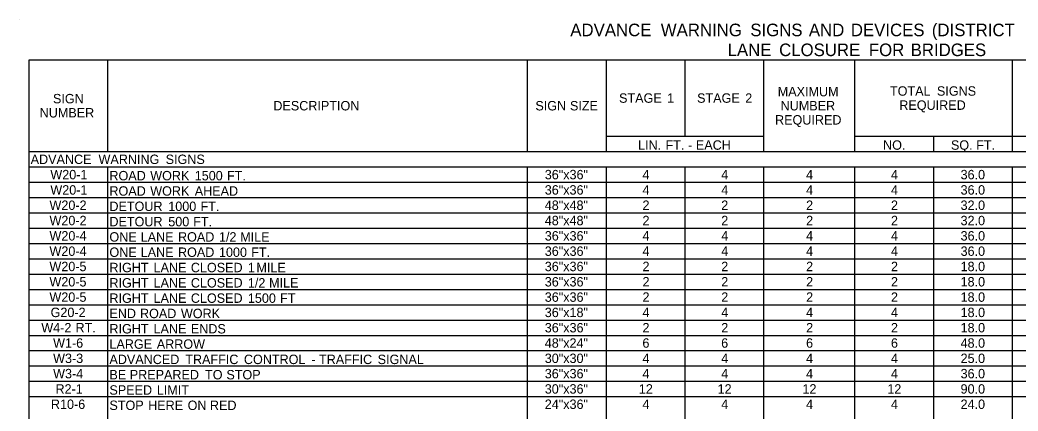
# Model space of a CAD drawing. Extents: x 542596 to 1930787, y -1948294 to 596640.
# Drawn here: x 546357 to 546993, y -1945349 to -1945100 of the extents above; entities that cross this region are included whole.
import ezdxf

# ---------------------------------------------------------------- set-up
doc = ezdxf.new("R2010")
doc.units = 0
doc.layers.add('Default', color=7, linetype='Continuous')

msp = doc.modelspace()

# ---------------------------------------------------------------- linework, layer by layer
at = {"layer": 'Default'}
for p, q in [((546356.95, -1945099.67), (546356.95, -1945099.67)), ((546362.8, -1945125.02), (547426.53, -1945125.02)), ((546362.8, -1945554.02), (546362.8, -1945125.02)), ((546362.8, -1945554.02), (546362.8, -1945125.02)), ((546413.02, -1945183.52), (546413.02, -1945125.02)), ((546680.65, -1945183.52), (546680.65, -1945125.02)), ((546730.87, -1945183.52), (546730.87, -1945125.02)), ((546781.08, -1945173.77), (546781.08, -1945125.02)), ((546831.29, -1945183.52), (546831.29, -1945125.02)), ((546889.3, -1945183.52), (546889.3, -1945125.02)), ((546989.73, -1945183.52), (546989.73, -1945125.02)), ((546730.87, -1945173.77), (546831.29, -1945173.77)), ((546831.29, -1945183.52), (546831.29, -1945173.77)), ((546889.3, -1945173.77), (547426.53, -1945173.77)), ((546939.52, -1945183.52), (546939.52, -1945173.77)), ((546362.8, -1945183.52), (547426.53, -1945183.52)), ((546831.29, -1945183.52), (547426.53, -1945183.52)), ((546362.8, -1945193.27), (547426.53, -1945193.27)), ((546413.02, -1945544.27), (546413.02, -1945193.27)), ((546413.02, -1945544.27), (546413.02, -1945193.27)), ((546680.65, -1945544.27), (546680.65, -1945193.27)), ((546680.65, -1945544.27), (546680.65, -1945193.27)), ((546730.87, -1945544.27), (546730.87, -1945193.27)), ((546730.87, -1945544.27), (546730.87, -1945193.27)), ((546781.08, -1945339.52), (546781.08, -1945193.27)), ((546781.08, -1945544.27), (546781.08, -1945193.27)), ((546831.29, -1945544.27), (546831.29, -1945193.27)), ((546831.29, -1945544.27), (546831.29, -1945193.27)), ((546889.3, -1945544.27), (546889.3, -1945193.27)), ((546939.52, -1945544.27), (546939.52, -1945193.27)), ((546939.52, -1945554.02), (546939.52, -1945193.27)), ((546989.73, -1945554.02), (546989.73, -1945193.27)), ((546989.73, -1945554.02), (546989.73, -1945193.27)), ((546362.8, -1945203.02), (547426.53, -1945203.02)), ((546362.8, -1945212.77), (547426.53, -1945212.77)), ((546362.8, -1945222.52), (547426.53, -1945222.52)), ((546362.8, -1945232.27), (547426.53, -1945232.27)), ((546362.8, -1945242.02), (547426.53, -1945242.02)), ((546362.8, -1945251.77), (547426.53, -1945251.77)), ((546362.8, -1945261.52), (547426.53, -1945261.52)), ((546362.8, -1945271.27), (547426.53, -1945271.27)), ((546362.8, -1945281.02), (547426.53, -1945281.02)), ((546362.8, -1945290.77), (547426.53, -1945290.77)), ((546362.8, -1945300.52), (547426.53, -1945300.52)), ((546362.8, -1945310.27), (547426.53, -1945310.27)), ((546362.8, -1945320.02), (547426.53, -1945320.02)), ((546362.8, -1945329.77), (547426.53, -1945329.77)), ((546362.8, -1945339.52), (547426.53, -1945339.52))]:
    msp.add_line(p, q, dxfattribs=at)

# ---------------------------------------------------------------- texts
for s, height, p in [('ADVANCE', 8, (546707.84, -1945110.01)), (' WARNING', 8, (546762.56, -1945110.01)), (' SIGNS', 8, (546819.63, -1945110.01)), (' AND', 8, (546856.97, -1945110.01)), (' DEVICES', 8, (546883.74, -1945110.01)), (' (DISTRICT', 8, (546935.37, -1945110.01)), ('LANE', 8, (546808.13, -1945122.68)), (' CLOSURE', 8, (546838.01, -1945122.68)), (' FOR', 8, (546895.22, -1945122.68)), (' BRIDGES', 8, (546921.86, -1945122.68)), ('MAXIMUM', 6, (546840.11, -1945148.27)), ('TOTAL', 6, (546911.67, -1945147.9)), (' SIGNS', 6, (546939.36, -1945147.9)), ('SIGN', 6, (546378, -1945152.77)), ('STAGE', 6, (546738.92, -1945152.4)), (' 1', 6, (546767.39, -1945152.4)), ('STAGE', 6, (546788.67, -1945152.4)), (' 2', 6, (546817.13, -1945152.4)), ('NUMBER', 6, (546369.53, -1945161.77)), ('DESCRIPTION', 6, (546518.52, -1945157.27)), ('SIGN', 6, (546685.57, -1945157.27)), (' SIZE', 6, (546705.4, -1945157.27)), ('NUMBER', 6, (546841.92, -1945157.27)), ('REQUIRED', 6, (546917.6, -1945156.9)), ('REQUIRED', 6, (546838.38, -1945166.27)), ('LIN.', 6, (546751.04, -1945182.32)), (' FT.', 6, (546766.3, -1945182.32)), (' -', 6, (546780.62, -1945182.32)), (' EACH', 6, (546785.68, -1945182.32)), ('NO.', 6, (546907.25, -1945182.32)), ('SQ.', 6, (546950.53, -1945182.32)), (' FT.', 6, (546964.39, -1945182.32)), ('ADVANCE', 6, (546363.78, -1945191.4)), (' WARNING', 6, (546404.82, -1945191.4)), (' SIGNS', 6, (546447.62, -1945191.4)), ('W20-1', 6, (546376.34, -1945201.15)), ('ROAD', 6, (546413.99, -1945201.82)), (' WORK', 6, (546437.77, -1945201.82)), (' 1500', 6, (546466.16, -1945201.82)), (' FT.', 6, (546486.72, -1945201.82)), ('36"x36"', 6, (546691.56, -1945201.15)), ('4', 6, (546753.85, -1945201.15)), ('4', 6, (546804.06, -1945201.15)), ('4', 6, (546858.17, -1945201.15)), ('4', 6, (546912.28, -1945201.15)), ('36.0', 6, (546956.67, -1945201.15)), ('W20-1', 6, (546376.34, -1945210.9)), ('ROAD', 6, (546413.99, -1945211.57)), (' WORK', 6, (546437.77, -1945211.57)), (' AHEAD', 6, (546466.16, -1945211.57)), ('36"x36"', 6, (546691.56, -1945210.9)), ('4', 6, (546753.85, -1945210.9)), ('4', 6, (546804.06, -1945210.9)), ('4', 6, (546858.17, -1945210.9)), ('4', 6, (546912.28, -1945210.9)), ('36.0', 6, (546956.67, -1945210.9)), ('W20-2', 6, (546375.79, -1945220.65)), ('DETOUR', 6, (546413.99, -1945221.32)), (' 1000', 6, (546449.28, -1945221.32)), (' FT.', 6, (546469.84, -1945221.32)), ('48"x48"', 6, (546691.56, -1945220.65)), ('2', 6, (546753.86, -1945220.65)), ('2', 6, (546804.08, -1945220.65)), ('2', 6, (546858.19, -1945220.65)), ('2', 6, (546912.3, -1945220.65)), ('32.0', 6, (546956.67, -1945220.65)), ('W20-2', 6, (546375.79, -1945230.4)), ('DETOUR', 6, (546413.99, -1945231.07)), (' 500', 6, (546449.28, -1945231.07)), (' FT.', 6, (546465.18, -1945231.07)), ('48"x48"', 6, (546691.56, -1945230.4)), ('2', 6, (546753.86, -1945230.4)), ('2', 6, (546804.08, -1945230.4)), ('2', 6, (546858.19, -1945230.4)), ('2', 6, (546912.3, -1945230.4)), ('32.0', 6, (546956.67, -1945230.4)), ('W20-4', 6, (546375.77, -1945240.15)), ('ONE', 6, (546413.99, -1945240.82)), (' LANE', 6, (546431.71, -1945240.82)), (' ROAD', 6, (546455.49, -1945240.82)), (' 1/2', 6, (546481.6, -1945240.82)), (' MILE', 6, (546495.13, -1945240.82)), ('36"x36"', 6, (546691.56, -1945240.15)), ('4', 6, (546753.85, -1945240.15)), ('4', 6, (546804.06, -1945240.15)), ('4', 6, (546858.17, -1945240.15)), ('4', 6, (546912.28, -1945240.15)), ('36.0', 6, (546956.67, -1945240.15)), ('W20-4', 6, (546375.77, -1945249.9)), ('ONE', 6, (546413.99, -1945250.57)), (' LANE', 6, (546431.71, -1945250.57)), (' ROAD', 6, (546455.49, -1945250.57)), (' 1000', 6, (546481.6, -1945250.57)), (' FT.', 6, (546502.16, -1945250.57)), ('36"x36"', 6, (546691.56, -1945249.9)), ('4', 6, (546753.85, -1945249.9)), ('4', 6, (546804.06, -1945249.9)), ('4', 6, (546858.17, -1945249.9)), ('4', 6, (546912.28, -1945249.9)), ('36.0', 6, (546956.67, -1945249.9)), ('W20-5', 6, (546375.74, -1945259.65)), ('RIGHT', 6, (546413.99, -1945260.32)), (' LANE', 6, (546439.9, -1945260.32)), (' CLOSED', 6, (546463.68, -1945260.32)), (' 1', 6, (546500.04, -1945260.32)), (' MILE', 6, (546505.49, -1945260.32)), ('36"x36"', 6, (546691.56, -1945259.65)), ('2', 6, (546753.86, -1945259.65)), ('2', 6, (546804.08, -1945259.65)), ('2', 6, (546858.19, -1945259.65)), ('2', 6, (546912.3, -1945259.65)), ('18.0', 6, (546956.67, -1945259.65)), ('W20-5', 6, (546375.74, -1945269.4)), ('RIGHT', 6, (546413.99, -1945270.07)), (' LANE', 6, (546439.9, -1945270.07)), (' CLOSED', 6, (546463.68, -1945270.07)), (' 1/2', 6, (546500.04, -1945270.07)), (' MILE', 6, (546513.57, -1945270.07)), ('36"x36"', 6, (546691.56, -1945269.4)), ('2', 6, (546753.86, -1945269.4)), ('2', 6, (546804.08, -1945269.4)), ('2', 6, (546858.19, -1945269.4)), ('2', 6, (546912.3, -1945269.4)), ('18.0', 6, (546956.67, -1945269.4)), ('W20-5', 6, (546375.74, -1945279.15)), ('RIGHT', 6, (546413.99, -1945279.82)), (' LANE', 6, (546439.9, -1945279.82)), (' CLOSED', 6, (546463.68, -1945279.82)), (' 1500', 6, (546500.04, -1945279.82)), (' FT', 6, (546520.6, -1945279.82)), ('36"x36"', 6, (546691.56, -1945279.15)), ('2', 6, (546753.86, -1945279.15)), ('2', 6, (546804.08, -1945279.15)), ('2', 6, (546858.19, -1945279.15)), ('2', 6, (546912.3, -1945279.15)), ('18.0', 6, (546956.67, -1945279.15)), ('G20-2', 6, (546376.49, -1945288.9)), ('END', 6, (546413.99, -1945289.57)), (' ROAD', 6, (546431.25, -1945289.57)), (' WORK', 6, (546457.35, -1945289.57)), ('36"x18"', 6, (546691.56, -1945288.9)), ('4', 6, (546753.85, -1945288.9)), ('4', 6, (546804.06, -1945288.9)), ('4', 6, (546858.17, -1945288.9)), ('4', 6, (546912.28, -1945288.9)), ('18.0', 6, (546956.67, -1945288.9)), ('W4-2', 6, (546370.57, -1945298.65)), (' RT.', 6, (546390.15, -1945298.65)), ('RIGHT', 6, (546413.99, -1945299.32)), (' LANE', 6, (546439.9, -1945299.32)), (' ENDS', 6, (546463.68, -1945299.32)), ('36"x36"', 6, (546691.56, -1945298.65)), ('2', 6, (546753.86, -1945298.65)), ('2', 6, (546804.08, -1945298.65)), ('2', 6, (546858.19, -1945298.65)), ('2', 6, (546912.3, -1945298.65)), ('18.0', 6, (546956.67, -1945298.65)), ('W1-6', 6, (546378.09, -1945308.4)), ('48"x24"', 6, (546691.56, -1945308.4)), ('6', 6, (546753.83, -1945308.4)), ('6', 6, (546804.04, -1945308.4)), ('6', 6, (546858.16, -1945308.4)), ('6', 6, (546912.27, -1945308.4)), ('48.0', 6, (546956.67, -1945308.4)), ('LARGE', 6, (546413.99, -1945309.07)), (' ARROW', 6, (546441.96, -1945309.07)), ('W3-3', 6, (546378.09, -1945318.15)), ('ADVANCED', 6, (546413.99, -1945318.82)), (' TRAFFIC', 6, (546460.13, -1945318.82)), (' CONTROL', 6, (546497.52, -1945318.82)), (' TRAFFIC', 6, (546545.4, -1945318.82)), (' SIGNAL', 6, (546582.79, -1945318.82)), ('30"x30"', 6, (546691.56, -1945318.15)), ('4', 6, (546753.85, -1945318.15)), ('4', 6, (546804.06, -1945318.15)), ('4', 6, (546858.17, -1945318.15)), ('4', 6, (546912.28, -1945318.15)), ('25.0', 6, (546956.67, -1945318.15)), (' -', 6, (546540.54, -1945318.82)), ('W3-4', 6, (546378.1, -1945327.9)), ('BE', 6, (546413.99, -1945328.57)), (' PREPARED', 6, (546424.73, -1945328.57)), (' TO', 6, (546472.74, -1945328.57)), (' STOP', 6, (546486.33, -1945328.57)), ('36"x36"', 6, (546691.56, -1945327.9)), ('4', 6, (546753.85, -1945327.9)), ('4', 6, (546804.06, -1945327.9)), ('4', 6, (546858.17, -1945327.9)), ('4', 6, (546912.28, -1945327.9)), ('36.0', 6, (546956.67, -1945327.9)), ('R2-1', 6, (546379.6, -1945337.65)), ('SPEED', 6, (546413.99, -1945338.32)), (' LIMIT', 6, (546441.97, -1945338.32)), ('30"x36"', 6, (546691.56, -1945337.65)), ('12', 6, (546751.53, -1945337.65)), ('12', 6, (546801.75, -1945337.65)), ('12', 6, (546855.86, -1945337.65)), ('12', 6, (546909.97, -1945337.65)), ('90.0', 6, (546956.67, -1945337.65)), ('R10-6', 6, (546376.69, -1945347.4)), ('STOP', 6, (546413.99, -1945348.07)), (' HERE', 6, (546436.45, -1945348.07)), (' ON', 6, (546461.63, -1945348.07)), (' RED', 6, (546475.85, -1945348.07)), ('24"x36"', 6, (546691.56, -1945347.4)), ('4', 6, (546753.85, -1945347.4)), ('4', 6, (546804.06, -1945347.4)), ('4', 6, (546858.17, -1945347.4)), ('4', 6, (546912.28, -1945347.4)), ('24.0', 6, (546956.67, -1945347.4))]:
    msp.add_text(s, height=height, dxfattribs=at).set_placement(p)

doc.saveas('drawing.dxf')
